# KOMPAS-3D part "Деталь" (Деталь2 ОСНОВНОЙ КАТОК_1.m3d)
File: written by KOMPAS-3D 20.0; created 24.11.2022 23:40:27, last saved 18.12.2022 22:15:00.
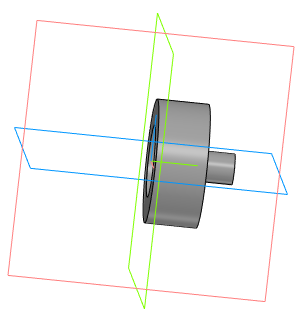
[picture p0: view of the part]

Document properties: Полное имя файла: C:\Users\Семья\Desktop\ДЕТАЛИ ДЛЯ СБОРЩИКА БОРЩЕВИКА\Деталь2 ОСНОВНОЙ КАТОК_1.m3d

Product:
- Part/product: Деталь
    Масса: 0.0293022

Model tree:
1. Эскиз:1
2. Элемент выдавливания:1
     Расстояние 1 = 10
3. Эскиз:2  (with: Элемент выдавливания:1)
4. Элемент выдавливания:2
     Расстояние 2 = 10
5. Эскиз:3  (with: Элемент выдавливания:1, Элемент выдавливания:2)
6. Элемент выдавливания:3
     Расстояние 2 = 6
7. Эскиз:5  (with: Элемент выдавливания:1, Элемент выдавливания:2)
8. Элемент выдавливания:5
     Расстояние 1 = 5
9. Элемент выдавливания:7  (with: Элемент выдавливания:5)
     Расстояние 1 = 1
10. Эскиз:8  (with: Элемент выдавливания:3)
11. Элемент выдавливания:10
     Расстояние 2 = 10
12. Эскиз:9  (with: Элемент выдавливания:3)
13. Элемент выдавливания:11
     Расстояние 2 = 4
14. Элемент выдавливания:12  (with: Элемент выдавливания:11)
     Расстояние 2 = 10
